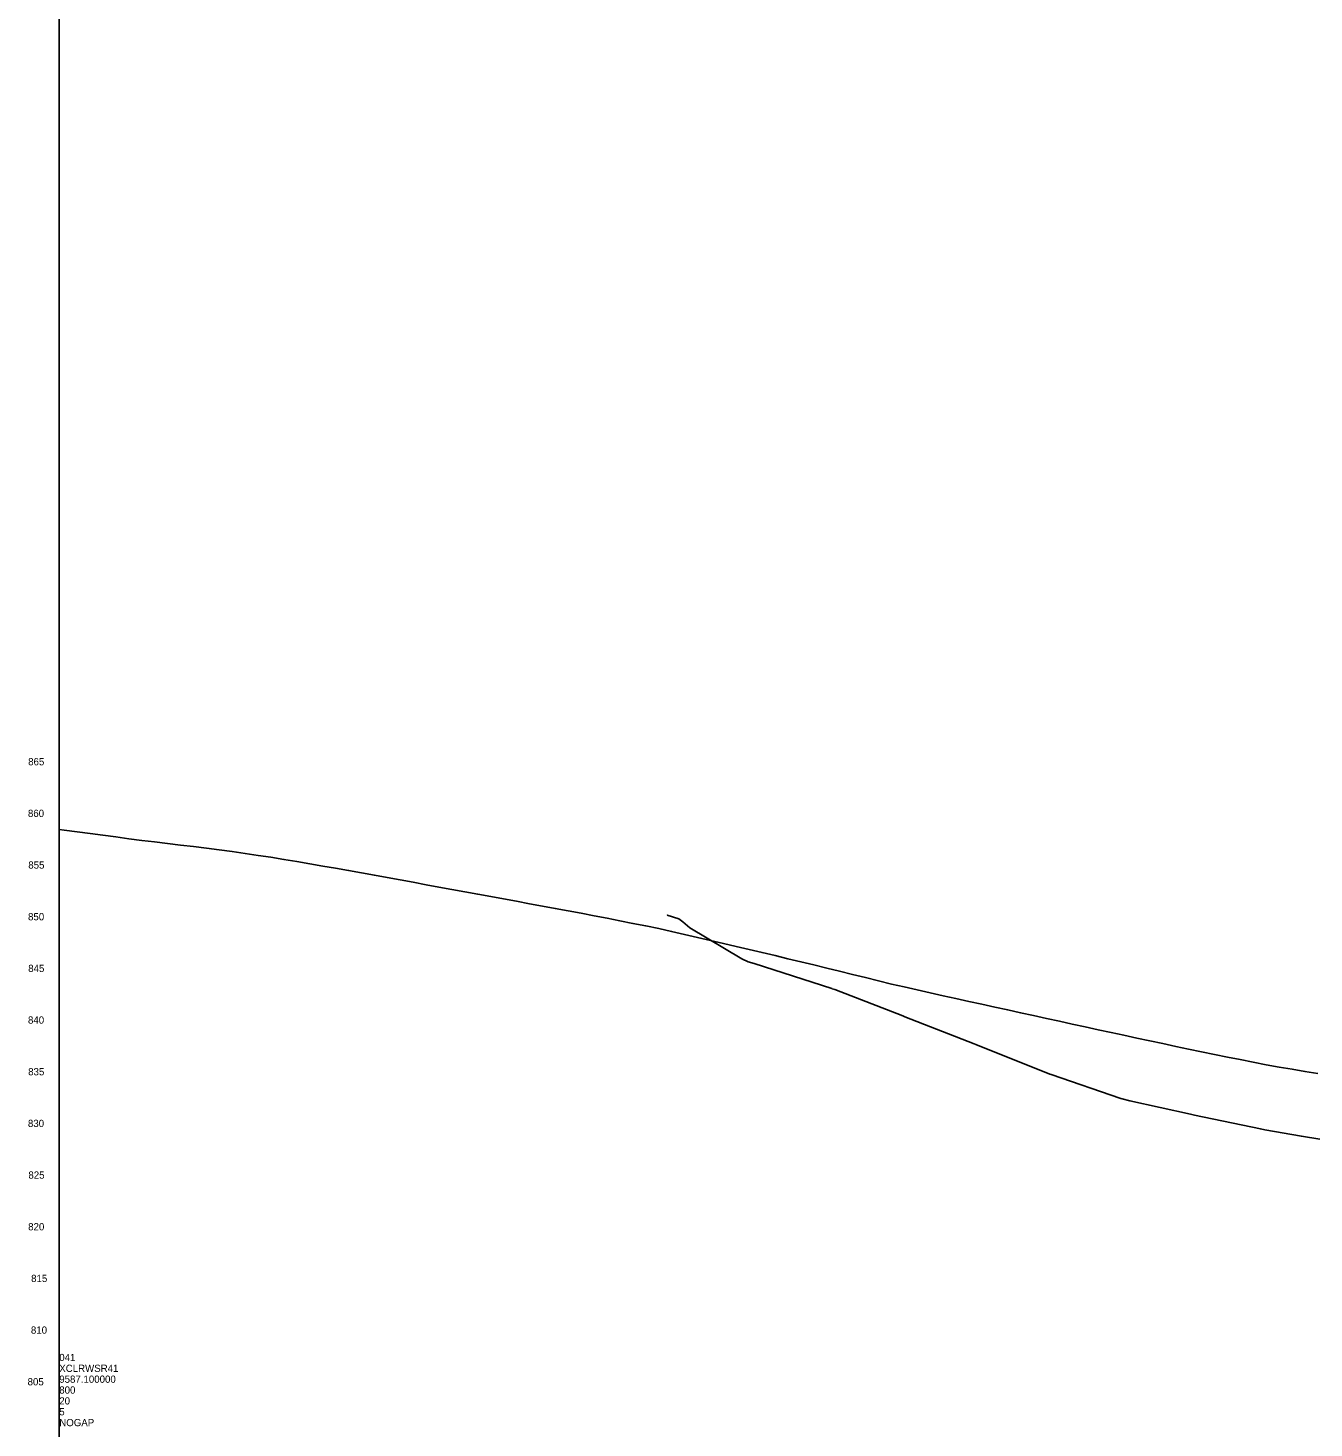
# Model space of a CAD drawing. Extents: x -12 to 4267, y -1006 to 1000.
# Drawn here: x -12 to 485, y 4 to 545 of the extents above; entities that cross this region are included whole.
import ezdxf

# ---------------------------------------------------------------- set-up
doc = ezdxf.new("R2010")
doc.units = 0
for name, color, linetype in [('GK_Cells', 7, 'Continuous'), ('PF_P_Sta_Elev_Text', 7, 'Continuous'), ('PF_X_Ground_Line', 7, 'Continuous'), ('UT_X_Water', 7, 'Continuous')]:
    doc.layers.add(name, color=color, linetype=linetype)

msp = doc.modelspace()

# ---------------------------------------------------------------- linework, layer by layer
at = {"layer": 'GK_Cells'}
msp.add_line((0, 0), (0, 1000), dxfattribs=at)
at = {"layer": 'PF_X_Ground_Line'}
msp.add_lwpolyline([(0, 235.09), (1.9, 234.85), (6.9, 234.2), (11.9, 233.55), (16.9, 232.9), (21.9, 232.25), (26.9, 231.6), (31.9, 230.95), (36.9, 230.33), (41.9, 229.74), (46.9, 229.13), (51.9, 228.52), (56.9, 227.9), (61.9, 227.29), (66.9, 226.58), (71.9, 225.85), (76.9, 225.11), (81.9, 224.38), (86.9, 223.6), (91.9, 222.74), (96.9, 221.88), (101.9, 221.02), (106.9, 220.16), (111.9, 219.3), (116.9, 218.39), (121.9, 217.46), (126.9, 216.54), (131.9, 215.62), (136.9, 214.7), (141.9, 213.78), (146.9, 212.86), (151.9, 211.94), (156.9, 211.02), (161.9, 210.1), (166.9, 209.19), (171.9, 208.27), (176.9, 207.35), (181.9, 206.43), (186.9, 205.5), (191.9, 204.58), (196.9, 203.65), (201.9, 202.73), (206.9, 201.77), (211.9, 200.78), (216.9, 199.79), (221.9, 198.8), (226.9, 197.8), (231.9, 196.81), (236.9, 195.68), (241.9, 194.51), (246.9, 193.34), (251.9, 192.17), (256.9, 191), (261.9, 189.82), (266.9, 188.65), (271.9, 187.48), (276.9, 186.32), (281.9, 185.15), (286.9, 183.98), (291.9, 182.78), (296.9, 181.54), (301.9, 180.29), (306.9, 179.05), (311.9, 177.81), (316.9, 176.57), (321.9, 175.33), (326.9, 174.19), (331.9, 173.07), (336.9, 171.95), (341.9, 170.83), (346.9, 169.7), (351.9, 168.58), (356.9, 167.49), (361.9, 166.39), (366.9, 165.29), (371.9, 164.2), (376.9, 163.1), (381.9, 162), (386.9, 160.92), (391.9, 159.84), (396.9, 158.76), (401.9, 157.67), (406.9, 156.59), (411.9, 155.51), (416.9, 154.43), (421.9, 153.35), (426.9, 152.27), (431.9, 151.18), (436.9, 150.1), (441.9, 149.06), (446.9, 148.07), (451.9, 147.08), (456.9, 146.08), (461.9, 145.08), (466.9, 144.08), (471.9, 143.21), (476.9, 142.37), (481.9, 141.53), (486.9, 140.68)], dxfattribs=at)
at = {"layer": 'UT_X_Water'}
msp.add_lwpolyline([(235.23, 202.02), (235.23, 202.02), (239.7, 200.55), (241.23, 199.37), (243.94, 197.15), (264.12, 185.07), (266.46, 183.88), (268.84, 183.26), (298.82, 173.55), (298.99, 173.52), (300.06, 173.19), (326.29, 163.03), (327.08, 162.66), (353.98, 152.16), (354.6, 151.9), (383.18, 140.46), (383.71, 140.32), (410.72, 131.02), (411.23, 130.85), (414.1, 130.19), (437.58, 124.98), (439.14, 124.59), (464.66, 119.23), (466.32, 118.94), (480.54, 116.44), (487.65, 115.24)], dxfattribs=at)

# ---------------------------------------------------------------- texts
at = {"layer": 'GK_Cells'}
for s, p in [('XCLRWSR41', (0, 25.2)), ('041', (0, 29.4)), ('9587.100000', (0, 21)), ('800', (0, 16.8)), ('5', (0, 8.4)), ('20', (0, 12.6)), ('NOGAP', (0, 4.2))]:
    msp.add_text(s, height=2.8, dxfattribs=at).set_placement(p)
at = {"layer": 'PF_P_Sta_Elev_Text'}
for s, p in [('865', (-12.03, 260)), ('860', (-12.12, 240)), ('855', (-11.99, 220)), ('850', (-12.08, 200)), ('845', (-12.01, 180)), ('840', (-12.1, 160)), ('835', (-12.03, 140)), ('830', (-12.12, 120)), ('825', (-11.94, 100)), ('820', (-12.03, 80)), ('815', (-10.88, 60)), ('810', (-10.97, 40)), ('805', (-12.25, 20))]:
    msp.add_text(s, height=2.8, dxfattribs=at).set_placement(p)

doc.saveas('drawing.dxf')
